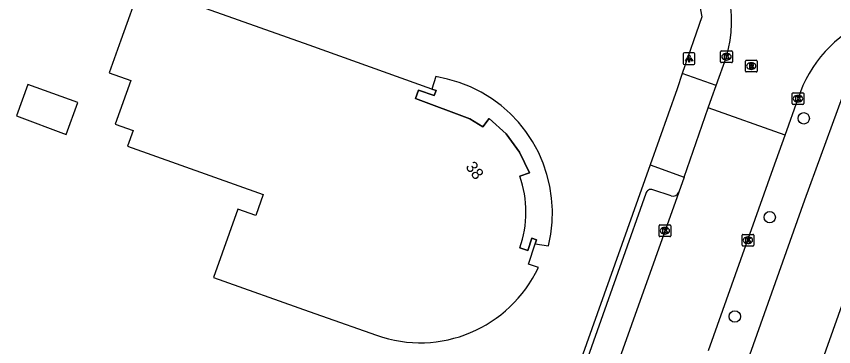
# Model space of a CAD drawing. Extents: x 155018 to 156648, y 383980 to 385733.
# Drawn here: x 155474.9 to 155544.9, y 385174.7 to 385203 of the extents above; entities that cross this region are included whole.
import ezdxf

# ---------------------------------------------------------------- set-up
doc = ezdxf.new("R2010")
doc.units = 0
for name, color, linetype in [('IMGEO_Boom', 7, 'Continuous'), ('IMGEO_Kolk', 7, 'Continuous'), ('IMGEO_Lichtpunt', 7, 'Continuous'), ('IMGEO_Pand', 7, 'Continuous'), ('IMGEO_Pand_nummerreeks', 7, 'Continuous'), ('IMGEO_Pand_overbouw', 7, 'Continuous'), ('IMGEO_Rijbaan_lokaal_gesloten', 7, 'Continuous'), ('IMGEO_Rioolput', 7, 'Continuous'), ('IMGEO_Voetpad_open', 7, 'Continuous')]:
    doc.layers.add(name, color=color, linetype=linetype)

msp = doc.modelspace()

# ---------------------------------------------------------------- linework, layer by layer
at = {"layer": 'IMGEO_Boom'}
for centre in [(155542.347, 385194.271), (155539.436, 385185.8), (155536.45, 385177.303)]:
    msp.add_circle(centre, 0.489, dxfattribs=at)
at = {"layer": 'IMGEO_Kolk'}
for p, q in [((155535.236, 385199.117), (155535.236, 385199.969)), ((155535.311, 385200.043), (155536.163, 385200.043)), ((155535.724, 385199.823), (155535.749, 385199.823)), ((155536.237, 385199.969), (155536.237, 385199.117)), ((155535.747, 385199.263), (155535.722, 385199.263)), ((155536.163, 385199.043), (155535.311, 385199.043)), ((155541.357, 385195.535), (155541.357, 385196.387)), ((155541.432, 385196.461), (155542.284, 385196.461)), ((155542.358, 385196.387), (155542.358, 385195.535)), ((155541.868, 385195.681), (155541.843, 385195.681)), ((155541.845, 385196.241), (155541.87, 385196.241)), ((155542.284, 385195.461), (155541.432, 385195.461)), ((155529.961, 385184.213), (155529.961, 385185.065)), ((155530.036, 385185.139), (155530.888, 385185.139)), ((155530.962, 385185.065), (155530.962, 385184.213)), ((155530.472, 385184.359), (155530.447, 385184.359)), ((155530.449, 385184.919), (155530.474, 385184.919)), ((155530.888, 385184.139), (155530.036, 385184.139)), ((155537.07, 385183.409), (155537.07, 385184.261)), ((155537.145, 385184.335), (155537.997, 385184.335)), ((155537.558, 385184.115), (155537.583, 385184.115)), ((155538.071, 385184.261), (155538.071, 385183.409)), ((155537.997, 385183.335), (155537.145, 385183.335)), ((155537.581, 385183.555), (155537.556, 385183.555))]:
    msp.add_line(p, q, dxfattribs=at)
for points in [[(155535.236, 385199.117), (155535.236, 385199.969)], [(155535.311, 385200.043), (155536.163, 385200.043)], [(155536.237, 385199.969), (155536.237, 385199.117)], [(155535.557, 385199.743), (155535.68, 385199.743), (155535.68, 385199.592), (155535.81, 385199.743), (155535.974, 385199.743), (155535.828, 385199.592), (155535.981, 385199.343), (155535.829, 385199.343), (155535.744, 385199.507), (155535.68, 385199.44), (155535.68, 385199.343), (155535.557, 385199.343), (155535.557, 385199.743)], [(155536.163, 385199.043), (155535.311, 385199.043)], [(155541.357, 385195.535), (155541.357, 385196.387)], [(155541.432, 385196.461), (155542.284, 385196.461)], [(155542.358, 385196.387), (155542.358, 385195.535)], [(155541.678, 385196.161), (155541.801, 385196.161), (155541.801, 385196.01), (155541.931, 385196.161), (155542.095, 385196.161), (155541.949, 385196.01), (155542.102, 385195.761), (155541.95, 385195.761), (155541.865, 385195.925), (155541.801, 385195.858), (155541.801, 385195.761), (155541.678, 385195.761), (155541.678, 385196.161)], [(155542.284, 385195.461), (155541.432, 385195.461)], [(155529.961, 385184.213), (155529.961, 385185.065)], [(155530.036, 385185.139), (155530.888, 385185.139)], [(155530.962, 385185.065), (155530.962, 385184.213)], [(155530.282, 385184.839), (155530.405, 385184.839), (155530.405, 385184.688), (155530.535, 385184.839), (155530.699, 385184.839), (155530.553, 385184.688), (155530.706, 385184.439), (155530.554, 385184.439), (155530.469, 385184.603), (155530.405, 385184.536), (155530.405, 385184.439), (155530.282, 385184.439), (155530.282, 385184.839)], [(155530.888, 385184.139), (155530.036, 385184.139)], [(155537.07, 385183.409), (155537.07, 385184.261)], [(155537.145, 385184.335), (155537.997, 385184.335)], [(155537.391, 385184.035), (155537.514, 385184.035), (155537.514, 385183.884), (155537.644, 385184.035), (155537.808, 385184.035), (155537.662, 385183.884), (155537.815, 385183.635), (155537.663, 385183.635), (155537.578, 385183.799), (155537.514, 385183.732), (155537.514, 385183.635), (155537.391, 385183.635), (155537.391, 385184.035)], [(155538.071, 385184.261), (155538.071, 385183.409)], [(155537.997, 385183.335), (155537.145, 385183.335)]]:
    msp.add_lwpolyline(points, dxfattribs=at)
for centre, start, end in [((155535.313, 385199.967), 91.55205, 178.44795), ((155535.313, 385199.967), 91.55205, 178.44795), ((155536.161, 385199.967), 1.55205, 88.44795), ((155536.161, 385199.967), 1.55205, 88.44795), ((155535.313, 385199.119), 181.55205, 268.44795), ((155535.313, 385199.119), 181.55205, 268.44795), ((155536.161, 385199.119), 271.55205, 358.44795), ((155536.161, 385199.119), 271.55205, 358.44795), ((155541.434, 385196.385), 91.55205, 178.44795), ((155541.434, 385196.385), 91.55205, 178.44795), ((155542.282, 385196.385), 1.55205, 88.44795), ((155542.282, 385196.385), 1.55205, 88.44795), ((155541.434, 385195.537), 181.55205, 268.44795), ((155541.434, 385195.537), 181.55205, 268.44795), ((155542.282, 385195.537), 271.55205, 358.44795), ((155542.282, 385195.537), 271.55205, 358.44795), ((155530.038, 385185.063), 91.55205, 178.44795), ((155530.038, 385185.063), 91.55205, 178.44795), ((155530.886, 385185.063), 1.55205, 88.44795), ((155530.886, 385185.063), 1.55205, 88.44795), ((155530.038, 385184.215), 181.55205, 268.44795), ((155530.038, 385184.215), 181.55205, 268.44795), ((155530.886, 385184.215), 271.55205, 358.44795), ((155530.886, 385184.215), 271.55205, 358.44795), ((155537.147, 385184.259), 91.55205, 178.44795), ((155537.147, 385184.259), 91.55205, 178.44795), ((155537.995, 385184.259), 1.55205, 88.44795), ((155537.995, 385184.259), 1.55205, 88.44795), ((155537.147, 385183.411), 181.55205, 268.44795), ((155537.147, 385183.411), 181.55205, 268.44795), ((155537.995, 385183.411), 271.55205, 358.44795), ((155537.995, 385183.411), 271.55205, 358.44795)]:
    msp.add_arc(centre, 0.0765, start, end, dxfattribs=at)
for centre, major_axis, ratio, start_param, end_param in [((155535.723, 385199.543), (-0.387, 0.002), 0.722429, 4.712389, 7.853982), ((155535.748, 385199.543), (-0.39, 0.002), 0.717154, 1.570796, 4.712389), ((155541.844, 385195.961), (-0.387, 0.002), 0.722429, 4.712389, 7.853982), ((155541.869, 385195.961), (-0.39, 0.002), 0.717154, 1.570796, 4.712389), ((155530.448, 385184.639), (-0.387, 0.002), 0.722429, 4.712389, 7.853982), ((155530.473, 385184.639), (-0.39, 0.002), 0.717154, 1.570796, 4.712389), ((155537.557, 385183.835), (-0.387, 0.002), 0.722429, 4.712389, 7.853982), ((155537.582, 385183.835), (-0.39, 0.002), 0.717154, 1.570796, 4.712389)]:
    msp.add_ellipse(centre, major_axis=major_axis, ratio=ratio, start_param=start_param, end_param=end_param, dxfattribs=at)
at = {"layer": 'IMGEO_Lichtpunt'}
for p, q in [((155532.032, 385199.783), (155532.032, 385198.976)), ((155532.032, 385199.783), (155532.032, 385198.976)), ((155532.934, 385199.878), (155532.126, 385199.878)), ((155532.934, 385199.878), (155532.126, 385199.878)), ((155533.028, 385198.976), (155533.028, 385199.783)), ((155533.028, 385198.976), (155533.028, 385199.783)), ((155532.126, 385198.882), (155532.934, 385198.882)), ((155532.126, 385198.882), (155532.934, 385198.882))]:
    msp.add_line(p, q, dxfattribs=at)
for points in [[(155532.406, 385199.447), (155532.445, 385199.419), (155532.257, 385199.157), (155532.219, 385199.184), (155532.406, 385199.447)], [(155532.508, 385199.399), (155532.555, 385199.399), (155532.555, 385199.077), (155532.508, 385199.077), (155532.508, 385199.399)], [(155532.618, 385199.419), (155532.656, 385199.446), (155532.843, 385199.184), (155532.804, 385199.156), (155532.618, 385199.419)]]:
    msp.add_lwpolyline(points, dxfattribs=at)
msp.add_circle((155532.531, 385199.581), 0.0994, dxfattribs=at)
for centre, start, end in [((155532.126, 385199.783), 90, 180), ((155532.126, 385199.783), 90, 180), ((155532.934, 385199.783), 0, 90), ((155532.934, 385199.783), 0, 90), ((155532.126, 385198.976), 180, 270), ((155532.126, 385198.976), 180, 270), ((155532.934, 385198.976), 270, 0), ((155532.934, 385198.976), 270, 360)]:
    msp.add_arc(centre, 0.0946, start, end, dxfattribs=at)
at = {"layer": 'IMGEO_Pand'}
for points in [[(155518.04, 385189.31), (155518.87, 385189.591), (155518.02, 385191.37), (155516.87, 385192.94), (155515.41, 385194.25), (155514.88, 385193.531), (155513.761, 385194.243), (155509.112, 385195.983), (155509.366, 385196.696), (155510.716, 385196.214), (155510.872, 385196.651), (155510.518, 385196.777), (155500, 385200.53), (155485.559, 385205.683), (155483.887, 385200.972), (155482.889, 385198.161), (155484.725, 385197.505), (155483.393, 385193.784), (155484.929, 385193.238), (155484.45, 385191.89), (155496.078, 385187.757), (155495.433, 385185.938), (155493.906, 385186.48), (155491.82, 385180.64), (155500, 385177.736), (155501.052, 385177.362), (155505.763, 385175.689)], [(155479.203, 385192.9), (155480.187, 385195.641), (155475.932, 385197.168), (155474.936, 385194.484), (155479.203, 385192.9)], [(155519.627, 385181.501), (155518.777, 385181.788), (155519.366, 385183.534), (155519.476, 385183.859), (155519.074, 385183.995), (155518.717, 385182.938), (155518.031, 385183.171)], [(155564.352, 385122.443), (155569.181, 385136.025), (155534.942, 385148.201), (155545.918, 385179.107), (155547.38, 385178.749), (155551.81, 385178.73), (155553.29, 385178.36), (155554, 385180.39), (155574.93, 385172.934), (155575.009, 385172.906), (155581.819, 385170.48), (155577.589, 385158.606), (155588.821, 385154.605), (155575.936, 385118.324), (155564.352, 385122.443)]]:
    msp.add_lwpolyline(points, dxfattribs=at)
for centre, radius, start, end in [((155509.351, 385186.253), 9.211, 340.44998, 19.38202), ((155509.492, 385186.235), 11.186, 250.52651, 334.96184)]:
    msp.add_arc(centre, radius, start, end, dxfattribs=at)
at = {"layer": 'IMGEO_Pand_overbouw'}
for points in [[(155518.031, 385183.171), (155518.717, 385182.938), (155519.074, 385183.995), (155519.476, 385183.859), (155519.366, 385183.534), (155520.483, 385183.339), (155520.687, 385184.349), (155520.802, 385185.372), (155520.828, 385186.402), (155520.764, 385187.431), (155520.61, 385188.449), (155520.368, 385189.451), (155520.04, 385190.427), (155519.628, 385191.371), (155519.135, 385192.276), (155518.565, 385193.134), (155517.922, 385193.939), (155517.212, 385194.685), (155516.439, 385195.366), (155515.61, 385195.978), (155514.73, 385196.514), (155513.807, 385196.972), (155512.848, 385197.348), (155511.86, 385197.639), (155510.85, 385197.842), (155510.518, 385196.777), (155510.872, 385196.651), (155510.716, 385196.214), (155509.366, 385196.696), (155509.112, 385195.983)], [(155509.112, 385195.983), (155513.761, 385194.243), (155514.88, 385193.531), (155515.41, 385194.25), (155516.87, 385192.94), (155518.02, 385191.37), (155518.87, 385189.591), (155518.04, 385189.31)]]:
    msp.add_lwpolyline(points, dxfattribs=at)
msp.add_arc((155509.351, 385186.253), 9.211, 340.44998, 19.38202, dxfattribs=at)
at = {"layer": 'IMGEO_Rijbaan_lokaal_gesloten'}
for points in [[(155534.852, 385197.073), (155535.739, 385199.542)], [(155534.179, 385195.179), (155534.489, 385196.063), (155534.852, 385197.073)], [(155540.748, 385192.836), (155541.87, 385195.982)], [(155532.098, 385189.247), (155534.179, 385195.179)], [(155540.748, 385192.836), (155534.179, 385195.179)], [(155534.193, 385174.381), (155539.728, 385189.975), (155540.748, 385192.836)], [(155532.098, 385189.247), (155531.642, 385187.947)], [(155531.642, 385187.947), (155515.445, 385142.497)]]:
    msp.add_lwpolyline(points, dxfattribs=at)
for centre, radius, start, end in [((155525.565, 385202.551), 10.61, 343.52506, 44.93221), ((155552.192, 385192.723), 10.824, 113.15785, 162.47826)]:
    msp.add_arc(centre, radius, start, end, dxfattribs=at)
at = {"layer": 'IMGEO_Rioolput'}
for p, q in [((155537.355, 385198.319), (155537.355, 385199.171)), ((155537.43, 385199.245), (155538.282, 385199.245)), ((155538.356, 385199.171), (155538.356, 385198.319)), ((155537.866, 385198.465), (155537.841, 385198.465)), ((155537.843, 385199.025), (155537.868, 385199.025)), ((155538.282, 385198.245), (155537.43, 385198.245))]:
    msp.add_line(p, q, dxfattribs=at)
for points in [[(155537.355, 385198.319), (155537.355, 385199.171)], [(155537.43, 385199.245), (155538.282, 385199.245)], [(155538.356, 385199.171), (155538.356, 385198.319)], [(155537.944, 385198.943), (155537.692, 385198.945), (155537.692, 385198.545)], [(155537.692, 385198.545), (155537.816, 385198.545), (155537.816, 385198.707), (155537.827, 385198.707)], [(155537.87, 385198.864), (155537.816, 385198.864), (155537.816, 385198.783)], [(155537.816, 385198.783), (155537.868, 385198.783)], [(155537.874, 385198.678), (155537.945, 385198.545), (155538.085, 385198.545), (155538.02, 385198.671)], [(155538.282, 385198.245), (155537.43, 385198.245)]]:
    msp.add_lwpolyline(points, dxfattribs=at)
for centre, radius, start, end in [((155537.432, 385199.169), 0.0765, 91.55205, 178.44795), ((155537.432, 385199.169), 0.0765, 91.55205, 178.44795), ((155538.28, 385199.169), 0.0765, 1.55205, 88.44795), ((155538.28, 385199.169), 0.0765, 1.55205, 88.44795), ((155537.826, 385198.654), 0.0533, 26.02933, 88.69889), ((155537.852, 385198.972), 0.19, 274.7715, 282.96867), ((155537.876, 385198.768), 0.0964, 77.00612, 93.18647), ((155537.89, 385198.825), 0.0378, 276.66336, 79.67722), ((155537.943, 385198.833), 0.109, 350.36119, 89.41601), ((155537.941, 385198.833), 0.112, 277.58423, 350.98172), ((155537.925, 385198.618), 0.108, 29.51342, 73.79051), ((155537.432, 385198.321), 0.0765, 181.55205, 268.44795), ((155537.432, 385198.321), 0.0765, 181.55205, 268.44795), ((155538.28, 385198.321), 0.0765, 271.55205, 358.44795), ((155538.28, 385198.321), 0.0765, 271.55205, 358.44795)]:
    msp.add_arc(centre, radius, start, end, dxfattribs=at)
for centre, major_axis, ratio, start_param, end_param in [((155537.842, 385198.745), (-0.387, 0.002), 0.722429, 4.712389, 7.853982), ((155537.867, 385198.745), (-0.39, 0.002), 0.717154, 1.570796, 4.712389)]:
    msp.add_ellipse(centre, major_axis=major_axis, ratio=ratio, start_param=start_param, end_param=end_param, dxfattribs=at)
at = {"layer": 'IMGEO_Voetpad_open'}
for points in [[(155500, 385219.714), (155501.291, 385219.137), (155532.69, 385207.961), (155533.612, 385202.973), (155531.952, 385198.111)], [(155551.448, 385201.401), (155546.604, 385198.733), (155542.42, 385187.249), (155529.708, 385151.464)], [(155531.952, 385198.111), (155531.502, 385196.793), (155529.193, 385190.291)], [(155534.852, 385197.073), (155531.952, 385198.111)], [(155529.193, 385190.291), (155513.774, 385146.868), (155514.242, 385146.673)], [(155529.193, 385190.291), (155532.098, 385189.247)], [(155531.001, 385187.629), (155529.425, 385188.161)], [(155528.826, 385187.833), (155514.242, 385146.673)]]:
    msp.add_lwpolyline(points, dxfattribs=at)
for centre, radius, start, end in [((155529.274, 385187.726), 0.461, 70.85887, 166.54953), ((155531.151, 385188.133), 0.525, 253.46394, 339.30807)]:
    msp.add_arc(centre, radius, start, end, dxfattribs=at)

# ---------------------------------------------------------------- texts
at = {"layer": 'IMGEO_Pand_nummerreeks'}
msp.add_text('38', height=1, rotation=306.81991, dxfattribs=at).set_placement((155513.343, 385190.112))

doc.saveas('drawing.dxf')
